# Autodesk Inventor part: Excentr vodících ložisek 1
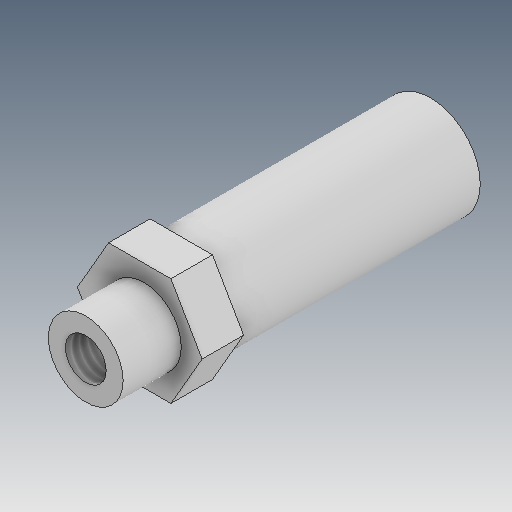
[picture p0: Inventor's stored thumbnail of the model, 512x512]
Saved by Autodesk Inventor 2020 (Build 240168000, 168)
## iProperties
Created: 2025-03
Part Number: Excentr vodících ložisek 1
Material: Všeobecné
Document SubType Name: Modeling
Designer: doma
Density: 1 g/cm^3
Appearance: Výchozí
Mass: 3.4428 g
Surface Area: 25.8057 cm^2
Volume: 3.4428 cm^3
Author: doma
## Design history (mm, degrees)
sketch "Náčrt1"
  geometry: C1 r 6 at (0, 0); 1 further point
  constraints: 1 centre point, 1 coincident
  dimensions: "d0" = 12 diameter of C1
extrude "Vysunutí1" new body sketch "Náčrt1" distance "d1" = 30; taper "d2" = 0 deg
sketch "Náčrt2"
  geometry: L1 (3.753, 6.5)-(7.506, 0); L2 (7.506, 0)-(3.753, -6.5); L3 (3.753, -6.5)-(-3.753, -6.5); L4 (-3.753, -6.5)-(-7.506, 0); L5 (-7.506, 0)-(-3.753, 6.5); L6 (-3.753, 6.5)-(3.753, 6.5); 2 further points
  constraints: 12 end point, 1 coincident, 13 other
  dimensions: "d3" = 13 distance between parallel lines of L3 L6
extrude "Vysunutí2" join sketch "Náčrt2" distance "d4" = 5; taper "d5" = 0 deg
sketch "Náčrt3"
  geometry: C1 r 4.5 at (0.5, 0); 1 further point
  constraints: 1 centre point
  dimensions: "d6" = 9 diameter of C1; "d7" = 0.5 distance of C1.centre point (0, 0)
extrude "Vysunutí3" join sketch "Náčrt3" distance "d8" = 7; taper "d9" = 0 deg
node "Pracovní bod1"
hole "Díra1" diameter "d12" = 4.917; stored, may be unused: countersink angle "d16" = 90 deg, drill point angle "d18" = 118 deg; dims "d13" = 12, "d14" = 14, "d15" = 8, "d17" = 17.1, "d30" = 10, "d31" = 10
node "Pracovní bod2"
hole "Díra2" diameter "d21" = 6.647; stored, may be unused: countersink angle "d25" = 90 deg, drill point angle "d27" = 118 deg; dims "d19" = 10, "d20" = 10, "d22" = 16, "d23" = 14, "d24" = 8, "d26" = 22.2
node "Těleso1"
